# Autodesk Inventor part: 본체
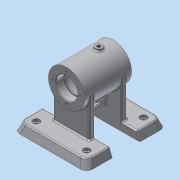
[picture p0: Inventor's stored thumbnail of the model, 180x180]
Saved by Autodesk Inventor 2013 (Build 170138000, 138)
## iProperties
Created: 2016-07
Part Number: 본체
Material: 알루미늄 6061
Document SubType Name: Modeling
Designer: Administrator
Density: 2.71 g/cm^3
Mass: 542.117 g
Surface Area: 571.142 cm^2
Volume: 200.043 cm^3
Author: Administrator
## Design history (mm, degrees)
sketch "스케치2"
  geometry: L1 (0, 0)-(70, 0); L2 (0, 0)-(0, 27); L3 (0, 27)-(70, 27); L4 (70, 0)-(70, 27); L5 (70, 16)-(58.3, 16); L6 (58, 15.7)-(58, 14); L7 (58, 14)-(56, 14); L8 (56, 14)-(56, 19); L9 (53, 22)-(17, 22); L10 (14, 19)-(14, 14); L11 (14, 14)-(12, 14); L12 (12, 14)-(12, 15.7); L13 (11.7, 16)-(0, 16); A1 r 3 centre (17, 19) between (17, 22) and (14, 19); A2 r 3 centre (53, 19) between (56, 19) and (53, 22); A3 r 0.3 centre (11.7, 15.7) between (12, 15.7) and (11.7, 16); A4 r 0.3 centre (58.3, 15.7) between (58.3, 16) and (58, 15.7)
  constraints: 26 end point, 8 point on circle, 8 tangent, 6 perpendicular, 5 parallel, 4 centre point, 2 equal radius, 2 point on line, 1 horizontal, 1 vertical
  dimensions: "d2" = 70 distance of L1.start L1.end; "d3" = 54 diameter of L3 L1; "d4" = 12 distance between parallel lines of L4 L6; "d5" = 32 diameter of L5 L1; "d6" = 28 diameter of L7 L1; "d7" = 2 distance between parallel lines of L6 L8; "d8" = 44 diameter of L9 L1; "d9" = 42 distance between parallel lines of L8 L10; "d10" = 32 diameter of L13 L1; "d11" = 28 diameter of L11 L1; "d12" = 12 distance between parallel lines of L2 L12; "d13" = 3 radius of A1; "d14" = 0.3 radius of A3
revolve "회전1" sketch "스케치2" stored, may be unused: angle "d15" = 90 deg
chamfer "모따기1" distance "d16" = 1; stored, may be unused: second distance "d17" = 2, angle "d18" = 45 deg
sketch "스케치3" dims "d19" = 42
  geometry: L1 (0, 0)-(0, 21); C1 r 17 at (0, 0) reference; C2 r 2 at (0, 21)
  constraints: 2 coincident, 2 end point, 1 centre point, 1 vertical, 1 vertical alignment, 2 other
  dimensions: "d21" = 4 diameter of C2
hole "구멍1" sketch "스케치3" at (0, 21) diameter "d22" = 3.242; stored, may be unused: countersink angle "d26" = 90 deg, drill point angle "d28" = 118 deg; dims "d23" = 8, "d24" = 4, "d25" = 2, "d27" = 10
node "작업 평면1"
node "작업 평면2"
sketch "스케치4"
  geometry: L1 (27, 70)-(-27, 70) reference; L2 (-50, 90)-(50, 90); L3 (50, 90)-(50, 55); L4 (50, 55)-(-50, 55); L5 (-50, 55)-(-50, 90); L6 (-27, 0)-(-27, 70) reference; L7 (27, 0)-(27, 70) reference; L8 (-27, 35)-(27, 35); 1 further point
  constraints: 10 end point, 2 midpoint, 2 parallel, 1 horizontal, 1 perpendicular
  dimensions: "d33" = 100 distance between parallel lines of L3 L5; "d35" = 50 distance from line of point (0, 0) L5; "d36" = 35 distance between parallel lines of L4 L2; "d37" = 55 distance between parallel lines of L8 L2
extrude "돌출1" join sketch "스케치4" distance "d38" = 12; taper "d39" = 0 deg
node "작업 평면3"
node "작업 평면4"
sketch "스케치6"
  geometry: L1 (0, 27)-(0, -27); L2 (0, 0)-(15.898, -25.441); A1 r 27 centre (0, 0) between (0, 27) and (0, -27) reference; 1 further point
  constraints: 4 end point, 2 point on circle, 1 midpoint, 1 vertical
  dimensions: "d48" = 30 distance of L2.start L2.end; "d49" = 32 deg angle of L2 L1
node "작업 평면5"
sketch "스케치7"
  geometry: C1 r 6 at (0, 0); 2 further points
  constraints: 1 centre point, 1 coincident
  dimensions: "d50" = 12 diameter of C1
extrude "돌출3" join sketch "스케치7" stored distance "d52" = 12; taper "d53" = 0 deg
fillet "모깎기1" dims "d54" = 2
sketch "스케치9"
  geometry: C1 r 6 at (0, 0) reference; 1 further point
hole "구멍3" sketch "스케치9" at (0, 0) diameter "d62" = 5.188; stored, may be unused: countersink angle "d66" = 90 deg, drill point angle "d68" = 118 deg; dims "d63" = 8, "d64" = 10, "d65" = 4, "d67" = 10
sketch "스케치10"
  geometry: L1 (100, 0)-(0, 0) reference; L2 (0, 0)-(0, 35) reference; C1 r 5 at (12.5, 12.5); C2 r 5 at (87.5, 12.5); 1 further point
  constraints: 2 centre point, 1 equal radius
  dimensions: "d69" = 10 diameter of C1; "d71" = 12.5 distance from line of L1 C1.centre; "d72" = 12.5 distance from line of C1.centre L2; "d73" = 75 distance of C2.centre C1.centre; "d74" = 12.5 distance from line of L1 C2.centre
hole "구멍4" sketch "스케치10" at (12.5, 12.5), (87.5, 12.5) diameter "d75" = 6; stored, may be unused: countersink angle "d79" = 90 deg, drill point angle "d81" = 118 deg; dims "d76" = 8, "d77" = 10, "d78" = 4, "d80" = 10
feature "면 기울기1" dims angle "d82" = 20 deg
feature "면 기울기2" dims angle "d84" = 20 deg
sketch "스케치11"
  geometry: L1 (0, 35)-(100, 35) reference; L2 (23, 35)-(77, 35); L3 (77, 35)-(77, 27); L4 (77, 27)-(23, 27); L5 (23, 27)-(23, 35); 1 further point
  constraints: 8 end point, 2 parallel, 1 horizontal, 1 perpendicular, 1 point on line
  dimensions: "d85" = 8 distance between parallel lines of L4 L1; "d86" = 54 distance between parallel lines of L3 L5; "d87" = 27 distance from line of point (50, 20) L5
extrude "돌출4" join sketch "스케치11" stored distance "d88" = 12; taper "d89" = 0 deg
node "작업 평면6"
sketch "스케치12"
  geometry: L1 (-31, -7)-(-31, 63) reference; L2 (0, 8)-(-58, 8) reference; L3 (0, 48)-(-58, 48) reference; L4 (-10, 8)-(-10, 48); 1 further point
  constraints: 2 end point, 2 point on line, 1 perpendicular
  dimensions: "d90" = 21 distance between parallel lines of L4 L1
feature "리브1" sketch "스케치12" dims "d91" = 1, "d92" = 8, "d93" = 0, "d94" = 0, "d95" = 1, "d96" = 1
sketch "스케치13"
  geometry: L1 (21.298, 40)-(21.298, 0) reference; L2 (7.798, 28)-(7.798, 12); L3 (14.798, 12)-(14.798, 28); L4 (-53.702, -15)-(-53.702, 55) reference; L5 (-53.702, 20)-(21.298, 20); L6 (43.298, 79.368)-(43.298, 40) reference; A1 r 3.5 centre (11.298, 12) between (7.798, 12) and (14.798, 12); A2 r 3.5 centre (11.298, 28) between (14.798, 28) and (7.798, 28); 1 further point
  constraints: 6 end point, 6 point on circle, 4 tangent, 2 centre point, 2 midpoint, 2 point on line, 1 equal radius, 1 vertical
  dimensions: "d99" = 23 dimension on A2 A1; "d101" = 8 vertical distance of L5.end A1.centre; "d102" = 3.5 radius of A1; "d103" = 32 distance from line of L6 A2.centre
extrude "돌출5" cut sketch "스케치13" stored distance "d104" = 12; taper "d105" = 0 deg
fillet "모깎기3" dims "d106" = 2
fillet "모깎기4" dims "d107" = 10
fillet "모깎기5" dims "d108" = 2
fillet "모깎기6" dims "d109" = 2
fillet "모깎기7" dims "d110" = 2
fillet "모깎기8" dims "d111" = 2
node "작업 평면7"
sketch "스케치14"
  geometry: L1 (27, 70)-(-27, 70) reference; C1 r 5 at (0, 48); 1 further point
  constraints: 1 centre point
  dimensions: "d113" = 0 horizontal distance of point (0, 0) C1.centre; "d114" = 10 diameter of C1; "d115" = 22 distance from line of C1.centre L1
extrude "돌출6" join sketch "스케치14" stored distance "d116" = 12; taper "d117" = 0 deg
sketch "스케치15"
  geometry: C1 r 5 at (0, 0) reference; 1 further point
hole "구멍5" sketch "스케치15" at (0, 0) diameter "d118" = 5.188; stored, may be unused: countersink angle "d122" = 90 deg, drill point angle "d124" = 118 deg; dims "d119" = 8, "d120" = 10, "d121" = 4, "d123" = 10
fillet "모깎기9" dims "d125" = 2
fillet "모깎기10" dims "d126" = 2
node "작업 평면8"
sketch "스케치16"
  geometry: L1 (-55.739, 3.002)-(-14.261, 3.002); L2 (-14.261, 3.002)-(-14.261, -3.002); L3 (-14.261, -3.002)-(-55.739, -3.002); L4 (-55.739, -3.002)-(-55.739, 3.002); L5 (-55.739, 0)-(-14.261, 0); L6 (-35, 3.002)-(-35, -3.002); L7 (-70, 27)-(-70, -27) reference; 1 further point
  constraints: 4 end point, 4 midpoint, 2 other
  dimensions: "d129" = 35 distance between parallel lines of L6 L7; "d130" = 0 distance from line of point (0, 0) L5
feature "엠보싱1" sketch "스케치16" dims "d2" = 70, "d3" = 54, "d4" = 12, "d5" = 32, "d6" = 28, "d7" = 2, "d8" = 44, "d9" = 42, "d10" = 32, "d11" = 28, "d12" = 12, "d13" = 3, "d14" = 0.3, "d131" = 0.5, "d132" = 0
fillet "모깎기11" dims "d133" = 2
node "솔리드1"
pattern_circular "원형 패턴1" dims angle "d30" = 360 deg
mirror "대칭1"
mirror "대칭2"
mirror "대칭3"
mirror "대칭4"
